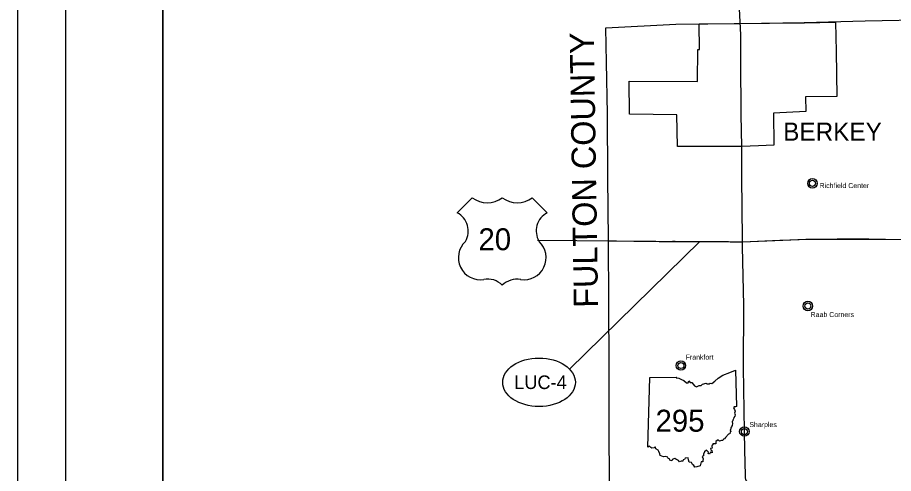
# Model space of a CAD drawing. Extents: x 0 to 750, y 0 to 507.
# Drawn here: x 0 to 180.7, y 239.9 to 334 of the extents above; entities that cross this region are included whole.
import ezdxf

# ---------------------------------------------------------------- set-up
doc = ezdxf.new("R2010")
doc.units = 0
for name, color, linetype in [('DV_X_Corp_Line', 7, 'Continuous'), ('GM_P_US_Alignment', 7, 'Continuous'), ('GM_X_Adjacent_County_Text', 7, 'Continuous'), ('GM_X_Corporation_Text', 7, 'Continuous'), ('GM_X_County', 7, 'Continuous'), ('GM_X_State_Route', 7, 'Continuous'), ('GM_X_US_Route', 7, 'Continuous'), ('SH_Border', 7, 'Continuous'), ('SH_Cut_Line', 7, 'Continuous'), ('SH_Data', 7, 'Continuous')]:
    doc.layers.add(name, color=color, linetype=linetype)

msp = doc.modelspace()

# ---------------------------------------------------------------- linework, layer by layer
at = {"layer": 'DV_X_Corp_Line'}
msp.add_lwpolyline([(126.19, 320.91), (140.32, 320.84), (140.39, 327.43), (140.71, 327.43), (140.65, 332.69), (162.39, 332.9), (168.75, 333.07), (168.88, 327.03), (169.06, 317.75), (162.61, 317.64), (162.64, 314.63), (155.99, 314.31), (156.03, 307.67), (152.88, 307.54), (149.42, 307.44), (136.19, 307.38), (136.02, 313.93), (126.25, 314.06)], close=True, dxfattribs=at)
for centre, radius in [((164.01, 299.81), 0.982), ((164.01, 299.81), 0.623), ((163.07, 274.5), 0.982), ((163.07, 274.5), 0.623), ((136.87, 262.22), 0.982), ((136.87, 262.22), 0.623), ((149.97, 248.6), 0.982), ((149.97, 248.6), 0.623)]:
    msp.add_circle(centre, radius, dxfattribs=at)
at = {"layer": 'GM_P_US_Alignment'}
msp.add_lwpolyline([(121.92, 287.94), (132.36, 287.84), (149.55, 287.75), (162.9, 288.3), (179.1, 288.29), (189.18, 288.13), (210.04, 288.31), (228.66, 288.19), (235.69, 288.01), (239.04, 288.66), (242.84, 289.34), (246.21, 288.69), (249.31, 288.69), (250.68, 289.04), (252.44, 289.82), (262.4, 290.25), (262.45, 289.38), (262.69, 289.12), (264.95, 287.17), (265.31, 286.65), (265.73, 285.61), (265.83, 284.12), (265.82, 283.58)], dxfattribs=at)
at = {"layer": 'GM_X_Corporation_Text'}
for p, q in [((93.83, 296.85), (90.72, 293.74)), ((93.83, 296.85), (90.72, 293.74)), ((109.3, 293.74), (106.19, 296.85)), ((109.3, 293.74), (106.19, 296.85)), ((130.03, 245.37), (130.43, 259.73)), ((130.03, 245.37), (130.43, 259.73))]:
    msp.add_line(p, q, dxfattribs=at)
for points in [[(130.43, 259.73), (136, 259.82), (135.91, 259.65), (136.44, 259.61), (137, 259.31), (137.47, 259.11), (138.05, 258.65), (138.39, 258.66), (138.54, 259.03), (138.8, 258.75), (139.12, 258.69), (139.66, 258.01), (140.11, 257.86), (140.65, 258.09), (141.05, 258.13), (141.34, 258.36), (142.11, 258.56), (142.32, 258.44), (142.72, 258.47), (142.93, 258.56), (143.28, 258.48), (143.9, 259), (144.54, 259.62), (145.53, 260.2), (147, 260.75), (148.16, 261.24), (148.33, 253.79)], [(130.43, 259.73), (136, 259.82), (135.91, 259.65), (136.44, 259.61), (137, 259.31), (137.47, 259.11), (138.05, 258.65), (138.39, 258.66), (138.54, 259.03), (138.8, 258.75), (139.12, 258.69), (139.66, 258.01), (140.11, 257.86), (140.65, 258.09), (141.05, 258.13), (141.34, 258.36), (142.11, 258.56), (142.32, 258.44), (142.72, 258.47), (142.93, 258.56), (143.28, 258.48), (143.9, 259), (144.54, 259.62), (145.53, 260.2), (147, 260.75), (148.16, 261.24), (148.33, 253.79)], [(148.33, 253.79), (148.16, 253.68), (147.89, 253.73), (147.71, 253.52), (147.93, 253.17), (148.04, 252.8), (147.94, 252.4), (148.04, 252.06), (147.97, 251.78), (147.81, 251.5), (147.75, 251.24), (147.6, 250.96), (147.62, 250.8), (147.48, 250.68), (147.51, 250.21), (147.44, 249.95), (147.46, 249.73), (147.24, 249.67), (147.29, 249.49), (147.15, 249.34), (147.18, 249.1), (147.02, 248.94), (147.17, 248.63), (147.05, 248.53), (146.95, 248.15), (146.66, 248.07), (146.1, 247.38), (145.9, 247.12), (145.67, 247.05), (145.55, 246.78), (145.27, 246.78), (144.85, 246.59), (144.58, 246.91), (144.11, 246.53), (144.06, 246.08), (143.46, 246.09), (143.48, 245.87), (143.35, 245.8), (143.22, 245.57), (143.29, 245.17), (143.01, 245.07), (143.05, 244.83), (143.23, 244.69), (143.31, 244.24), (143.01, 244.33), (142.76, 243.96), (142.51, 244.05), (142.6, 244.37), (142.17, 244.75), (141.77, 244.44), (141.56, 243.95), (141.56, 243.62), (141.26, 243.42), (141.45, 242.95), (141.42, 242.63), (141.42, 242.33), (141.05, 242.34), (140.82, 241.51)], [(148.33, 253.79), (148.16, 253.68), (147.89, 253.73), (147.71, 253.52), (147.93, 253.17), (148.04, 252.8), (147.94, 252.4), (148.04, 252.06), (147.97, 251.78), (147.81, 251.5), (147.75, 251.24), (147.6, 250.96), (147.62, 250.8), (147.48, 250.68), (147.51, 250.21), (147.44, 249.95), (147.46, 249.73), (147.24, 249.67), (147.29, 249.49), (147.15, 249.34), (147.18, 249.1), (147.02, 248.94), (147.17, 248.63), (147.05, 248.53), (146.95, 248.15), (146.66, 248.07), (146.1, 247.38), (145.9, 247.12), (145.67, 247.05), (145.55, 246.78), (145.27, 246.78), (144.85, 246.59), (144.58, 246.91), (144.11, 246.53), (144.06, 246.08), (143.46, 246.09), (143.48, 245.87), (143.35, 245.8), (143.22, 245.57), (143.29, 245.17), (143.01, 245.07), (143.05, 244.83), (143.23, 244.69), (143.31, 244.24), (143.01, 244.33), (142.76, 243.96), (142.51, 244.05), (142.6, 244.37), (142.17, 244.75), (141.77, 244.44), (141.56, 243.95), (141.56, 243.62), (141.26, 243.42), (141.45, 242.95), (141.42, 242.63), (141.42, 242.33), (141.05, 242.34), (140.82, 241.51)], [(140.82, 241.51), (140.17, 241.35), (139.72, 241.26), (139.56, 241.63), (139.24, 241.83), (139.03, 242.21), (138.56, 242.26), (138.45, 242.78), (138.4, 243.2), (137.77, 243.09), (137.59, 242.84), (137.37, 242.77), (137.24, 242.51), (136.93, 242.49), (136.6, 242.37), (136.39, 242.62), (135.85, 242.87), (135.61, 243.01), (135.1, 242.8), (134.99, 242.56), (134.59, 242.67), (134.49, 242.94), (134.25, 243.02), (134.2, 243.3), (133.68, 243.46), (133.28, 243.4), (132.57, 243.63), (132.53, 244), (132.29, 244.46), (132.17, 244.78), (131.72, 245.02), (131.63, 245.4), (131.49, 245.39), (131.36, 245.24), (130.86, 245.17), (130.67, 245.32), (130.39, 245.58), (130.03, 245.37)], [(140.82, 241.51), (140.17, 241.35), (139.72, 241.26), (139.56, 241.63), (139.24, 241.83), (139.03, 242.21), (138.56, 242.26), (138.45, 242.78), (138.4, 243.2), (137.77, 243.09), (137.59, 242.84), (137.37, 242.77), (137.24, 242.51), (136.93, 242.49), (136.6, 242.37), (136.39, 242.62), (135.85, 242.87), (135.61, 243.01), (135.1, 242.8), (134.99, 242.56), (134.59, 242.67), (134.49, 242.94), (134.25, 243.02), (134.2, 243.3), (133.68, 243.46), (133.28, 243.4), (132.57, 243.63), (132.53, 244), (132.29, 244.46), (132.17, 244.78), (131.72, 245.02), (131.63, 245.4), (131.49, 245.39), (131.36, 245.24), (130.86, 245.17), (130.67, 245.32), (130.39, 245.58), (130.03, 245.37)]]:
    msp.add_lwpolyline(points, dxfattribs=at)
for centre, radius, start, end in [((96.92, 300.78), 5, 231.813, 308.187), ((96.92, 300.78), 5, 231.813, 308.187), ((103.1, 300.78), 5, 231.813, 308.187), ((103.1, 300.78), 5, 231.813, 308.187), ((88.77, 289.99), 4.23, 329.1175, 62.6108), ((88.77, 289.99), 4.23, 329.1175, 62.6108), ((111.24, 289.99), 4.23, 117.3892, 210.8825), ((111.24, 289.99), 4.23, 117.3892, 210.8825), ((95.51, 284.48), 4.56, 133.0046, 278.7282), ((95.51, 284.48), 4.56, 133.0046, 278.7282), ((104.5, 284.48), 4.56, 261.2718, 46.9954), ((104.5, 284.48), 4.56, 261.2718, 46.9954), ((97.04, 275.98), 4.08, 43.4177, 101.8742), ((97.04, 275.98), 4.08, 43.4177, 101.8742), ((103.06, 275.71), 4.33, 79.9613, 134.7468), ((103.06, 275.71), 4.33, 79.9613, 134.7468)]:
    msp.add_arc(centre, radius, start, end, dxfattribs=at)
at = {"layer": 'GM_X_County'}
msp.add_lwpolyline([(122.16, 238.43), (122.06, 248.84), (122.05, 258.67), (122.04, 262.21), (122.03, 275.06), (121.92, 288.14), (121.82, 301.04), (121.7, 314.15), (121.5, 324.72), (121.36, 331.88), (135.81, 332.68), (149.12, 332.77), (162.29, 332.97), (174.88, 333.37), (188.86, 333.6)], dxfattribs=at)
at = {"layer": 'GM_X_State_Route'}
for points in [[(149.23, 327.39), (149.23, 330.47), (148.98, 335.83)], [(149.24, 325.13), (149.23, 327.25), (149.23, 327.39)], [(149.42, 307.44), (149.34, 313.97), (149.24, 325.13)], [(149.44, 301.05), (149.44, 301.05), (149.42, 307.44), (149.42, 307.44)], [(149.55, 288.29), (149.44, 301.05)], [(149.55, 287.75), (149.55, 288.29)], [(149.57, 286.71), (149.55, 287.75)], [(150.75, 238.09), (150.44, 238.39), (150.26, 238.71), (150.18, 239.04), (150.17, 239.56), (150.08, 244.83), (150.01, 248.63), (149.82, 261.84), (149.83, 274.65), (149.57, 286.71)]]:
    msp.add_lwpolyline(points, dxfattribs=at)
at = {"layer": 'GM_X_US_Route'}
for points in [[(107.31, 288.08), (131.7, 287.85), (132.36, 287.84), (135.14, 287.85), (135.69, 287.85), (136.47, 287.84), (138.33, 287.81), (138.96, 287.8), (142.13, 287.8), (142.7, 287.8), (145.34, 287.78), (146.05, 287.78), (146.71, 287.78), (147.04, 287.77)], [(147.04, 287.77), (147.38, 287.77), (149.09, 287.76), (149.55, 287.75)], [(149.55, 287.75), (149.55, 287.75), (151.15, 287.8)], [(151.15, 287.8), (152.65, 287.85), (157.28, 288.08), (159.35, 288.14), (162.64, 288.3), (162.9, 288.3)], [(162.9, 288.3), (169.08, 288.36), (173.6, 288.35), (175.62, 288.35), (179.1, 288.29), (183.17, 288.19), (185.89, 288.16), (189.18, 288.13), (198.12, 288.08), (202.42, 288.09)]]:
    msp.add_lwpolyline(points, dxfattribs=at)
at = {"layer": 'SH_Border'}
for points in [[(10, 430), (30, 430), (30, 10), (10, 10)], [(30, 430), (670, 430), (670, 10), (30, 10)]]:
    msp.add_lwpolyline(points, close=True, dxfattribs=at)
at = {"layer": 'SH_Cut_Line'}
msp.add_lwpolyline([(0, 0), (680, 0), (680, 440), (0, 440)], close=True, dxfattribs=at)
at = {"layer": 'SH_Data'}
msp.add_line((113.88, 261.5), (140.76, 287.8), dxfattribs=at)
msp.add_ellipse((107.6, 258.77), major_axis=(7.5, 0), ratio=0.666667, dxfattribs=at)

# ---------------------------------------------------------------- texts
at = {"layer": 'DV_X_Corp_Line'}
for s, height, p in [('Richfield Center', 1.0417, (165.49, 298.83)), ('Raab Corners', 1.0417, (163.64, 272.22)), ('Frankfort', 1.042, (137.85, 263.44)), ('Sharples', 1.042, (150.99, 249.52))]:
    msp.add_text(s, height=height, rotation=0, dxfattribs=at).set_placement(p)
at = {"layer": 'GM_X_Adjacent_County_Text'}
msp.add_text('FULTON COUNTY', height=5, rotation=90.8861, dxfattribs=at).set_placement((119.79, 274.17))
at = {"layer": 'GM_X_Corporation_Text'}
msp.add_text('BERKEY', height=3.75, rotation=0, dxfattribs=at).set_placement((157.98, 308.6))
for s, p in [('20', (95.1, 286.01)), ('295', (131.64, 248.57))]:
    msp.add_text(s, height=4.528, dxfattribs=at).set_placement(p)
at = {"layer": 'SH_Data'}
msp.add_text('LUC-4', height=2.8, dxfattribs=at).set_placement((102.49, 257.37))

doc.saveas('drawing.dxf')
